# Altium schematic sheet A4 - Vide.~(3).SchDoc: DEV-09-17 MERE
size A4; Date: 22/11/2017; Organization: Altium Limited; Address1: L3, 12a Rodborough Rd; Address2: Frenchs Forest; Address3: NSW; Address4: Australia 2086; Revision: 1.0; SheetNumber: 1; SheetTotal: 1; PageSetup: Record=PageOptions¦CenterHorizontal=True¦CenterVertical=True¦PrintScale=0.97¦XCorrection=1.00¦YCorrection=1.00¦PrintKind=0¦BorderSize=5000000¦LeftOffset=0¦BottomOffset=0¦Orientation=2¦PaperLength=1000¦PaperWidth=1000¦Scale=100¦PaperSource=7¦PrintQuality=-3¦MediaType=1¦DitherType=10¦PaperKind=A4¦PrintScaleMode=1
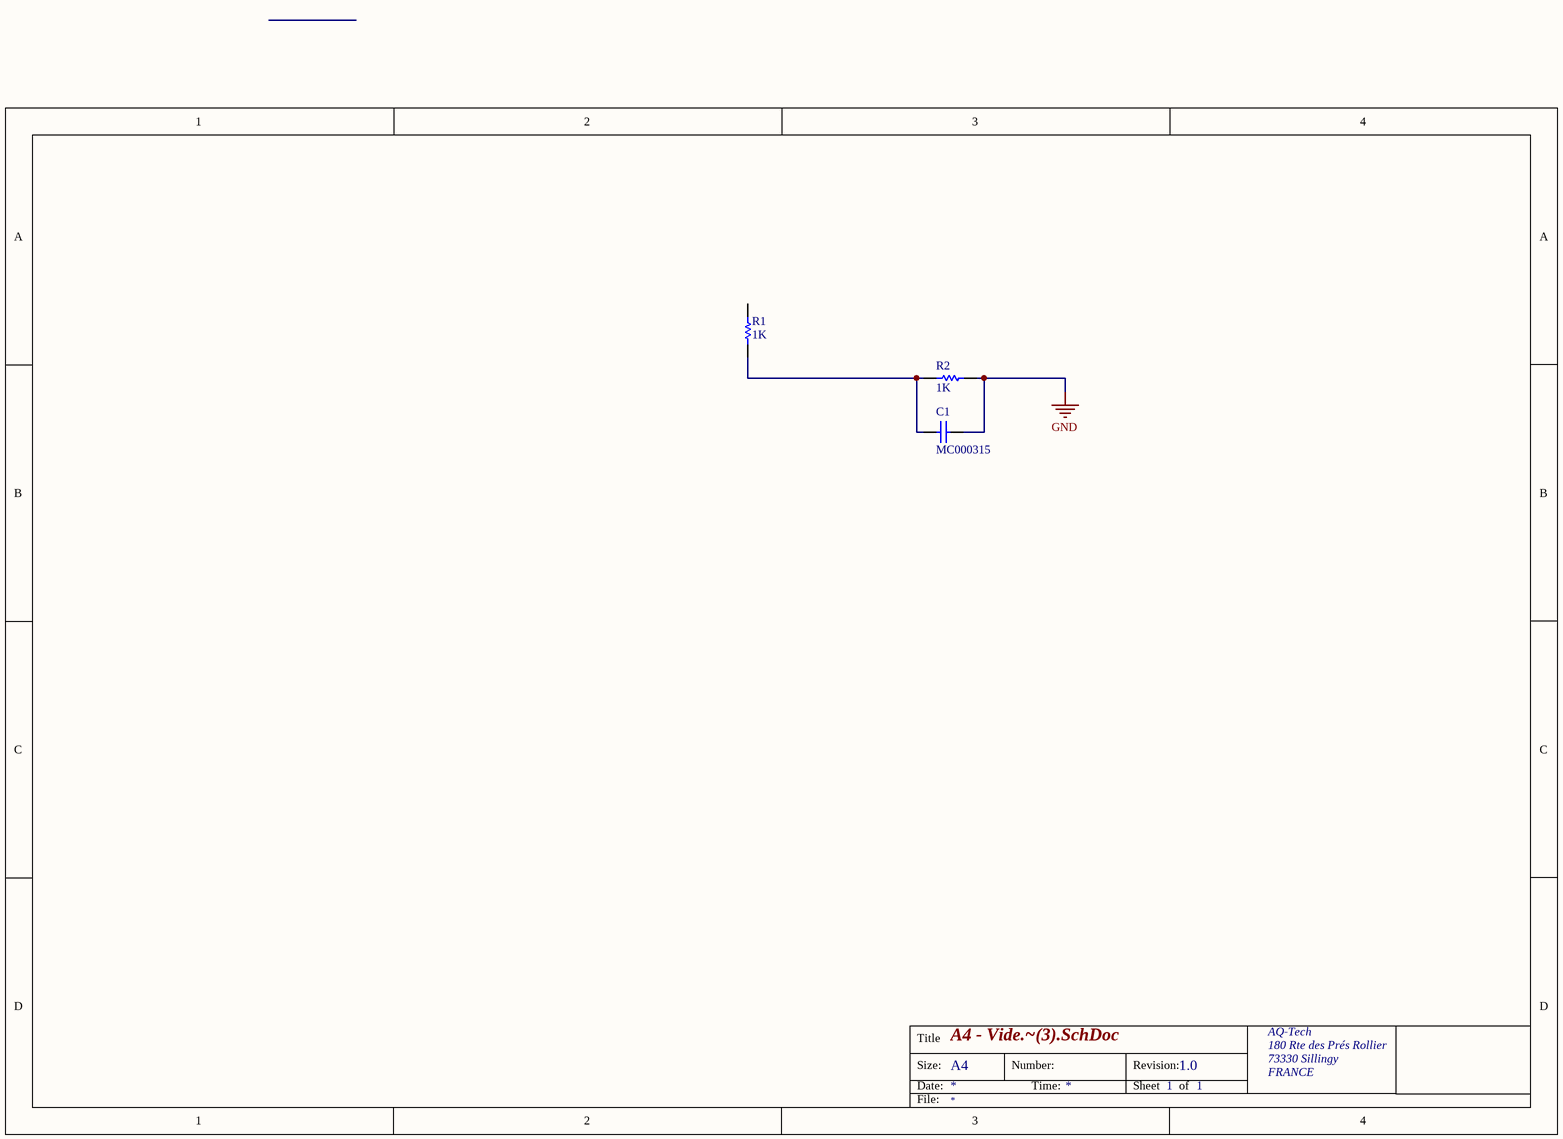
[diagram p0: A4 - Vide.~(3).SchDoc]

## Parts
C1  MC000315  [CAPC0603X33X15NL03T05]
R1  value 1K  (hidden comment: Resistor)
R2  value 1K  (hidden comment: Resistor)

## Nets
GND: C1.2 R2.2
NetC1_1: C1.1 R1.2 R2.1

Not connected (* = marked no-connect by the designer): R1 1

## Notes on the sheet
- Title
- Size:
- Date:
- A4
- Number:
- Time:
- Revision:
- Sheet
- of
- AQ-Tech
- 180 Rte des Prés Rollier
- 73330 Sillingy
- FRANCE
- File:

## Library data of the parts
C1 = CMP-2010-01738-1: Manufacturer: Multicomp
R1 R2 = Resistor: TC1: 0; SimulationGenericComponent: True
